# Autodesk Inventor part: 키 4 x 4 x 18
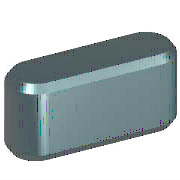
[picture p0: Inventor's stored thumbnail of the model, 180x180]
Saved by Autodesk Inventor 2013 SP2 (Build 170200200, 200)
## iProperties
IsCustomPart: 1
Created: 2012-02
Part Number: 키 4 x 4 x 18
Material: 강철, 연강
Description: 키 및 해당 키홈
Document SubType Name: Modeling
Standard: KS B 1311
Designer: mduedu
Standards Organization: KS
Language: ko-KR
Size Designation: 4 x 4 x 18
Categories: <MemberInstance><Categories><Category DisplayName="샤프트 부품" InternalName="7f7aeb1f-a693-4053-b835-cee3144e0d98" Mnemonic="SHFT"><Category DisplayName="키" Interna
Density: 7.86 g/cm^3
Mass: 2.13606 g
Surface Area: 2.87354 cm^2
Volume: 0.271763 cm^3
Author: mduedu
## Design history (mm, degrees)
workplane "Work Plane1"
workplane "Work Plane2"
sketch "스케치1"
  geometry: L1 (2, 2)-(16, 2); L2 (16, -2)-(2, -2); L3 (0, 9.4)-(0, -7.4) reference; L4 (-5, 0)-(30, 0) reference; L5 (18, 0)-(18, 7); A1 r 2 centre (2, 0) between (2, 2) and (2, -2); A2 r 2 centre (16, 0) between (16, -2) and (16, 2)
  constraints: 6 end point, 5 point on circle, 4 tangent, 3 point on line, 2 centre point, 1 horizontal, 1 parallel, 1 perpendicular
  dimensions: "d0" = 2 radius of A1 (= 0.5 x PB); "d13" = 2 radius of A2 (= 0.5 x PB); "d14" = 18 distance between parallel lines of L5 L3 (= NLG)
extrude "본체1" new body sketch "스케치1" taper "d3" = 0 deg; stored distance "d4" = 10
workplane "Work Plane3"
body "Solid1"
chamfer "모따기1" distance "d8" = 0.25 (= PHH); stored, may be unused: second distance "d9" = 0.25 (= PHH), angle "d15" = 45 deg
other parameters: "d1" = -2.5 (= -PNT), "d2" = 1.5 (= PH - PNT), "NLG" = 18 [user parameter; used in 3 equation terms], "PB" = 4 [user parameter; used in 2 equation terms], "PNT" = 2.5 [user parameter; used in 2 equation terms], "PH" = 4 [user parameter; used in 1 equation term], "PHH" = 0.25 [user parameter; used in 2 equation terms], "d10" = 0, "d16" = 0, "d17" = 0, "d18" = 0, "PLB2" = 18 (= NLG) [user parameter], "WDMAX" = 12 [user parameter], "PLB1" = 18 (= NLG) [user parameter], "RR" = 0.08 [user parameter], "PUEB" = 1.8 [user parameter]
